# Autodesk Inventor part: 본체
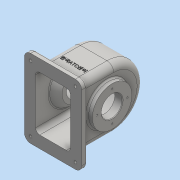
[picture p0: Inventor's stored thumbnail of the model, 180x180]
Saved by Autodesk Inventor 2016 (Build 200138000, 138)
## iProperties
Created: 2018-11
Part Number: 본체
Material: 일반
Document SubType Name: Modeling
Designer: user
Density: 1 g/cm^3
Appearance: 기본값
Mass: 404.475 g
Surface Area: 1182.21 cm^2
Volume: 404.475 cm^3
Author: user
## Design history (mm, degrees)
sketch "스케치1"
  geometry: L1 (-55, -75)-(55, -75); L2 (55, -75)-(55, 75); L3 (55, 75)-(-55, 75); L4 (-55, 75)-(-55, -75); L5 (-55, -75)-(55, 75); L6 (55, -75)-(-55, 75); 1 further point
  constraints: 12 end point, 2 midpoint, 2 parallel, 1 horizontal, 1 perpendicular
  dimensions: "d0" = 110 distance of L3.end L2.end; "d1" = 150 distance of L1.end L2.end
extrude "돌출1" new body sketch "스케치1" distance "d2" = 10; taper "d3" = 0 deg
sketch "스케치2"
  geometry: L1 (-38.5, 58)-(38.5, 58); L2 (38.5, 58)-(38.5, -58); L3 (38.5, -58)-(-38.5, -58); L4 (-38.5, -58)-(-38.5, 58); L5 (-38.5, 58)-(38.5, -58); L6 (38.5, 58)-(-38.5, -58); 1 further point
  constraints: 12 end point, 2 midpoint, 2 parallel, 1 horizontal, 1 perpendicular
  dimensions: "d4" = 77 distance of L2.end L3.end; "d5" = 116 distance of L1.end L2.end
extrude "돌출2" join sketch "스케치2" distance "d6" = 126; taper "d7" = 0 deg
fillet "모깎기1" dims "d8" = 58
feature "쉘1" dims "d13" = 6, "d14" = 5, "d15" = 10
sketch "스케치5"
  geometry: L1 (-17, -10)-(133, -10) reference; C1 r 38 at (58, 55); 2 further points
  constraints: 1 centre point, 1 midpoint, 1 vertical alignment
  dimensions: "d16" = 76 diameter of C1; "d17" = 65 distance from line of C1.centre L1
extrude "돌출4" join sketch "스케치5" distance "d18" = 10; taper "d19" = 0 deg
sketch "스케치6"
  geometry: L1 (-17, -10)-(133, -10) reference; C1 r 38 at (58, 55); 2 further points
  constraints: 1 centre point, 1 midpoint, 1 vertical alignment
  dimensions: "d20" = 76 diameter of C1; "d21" = 65 distance from line of L1 C1.centre
extrude "돌출5" join sketch "스케치6" distance "d22" = 5; taper "d23" = 0 deg
node "작업 평면1"
sketch "스케치7"
  geometry: C1 r 6 at (0, 0); 1 further point
  constraints: 1 centre point, 1 coincident
  dimensions: "d25" = 12 diameter of C1
extrude "돌출6" join sketch "스케치7" stored distance "d26" = 5; taper "d27" = 5 deg
sketch "스케치8"
  geometry: 2 further points
  constraints: 1 coincident
hole "구멍1" sketch "스케치8" at (0, 0) diameter "d28" = 4.459; stored, may be unused: countersink angle "d32" = 90 deg, drill point angle "d34" = 118 deg; dims "d29" = 20, "d30" = 4, "d31" = 2, "d33" = 12.8
node "작업 평면2"
sketch "스케치10"
  geometry: C1 r 28 at (0, 0); 1 further point
  constraints: 1 centre point, 1 vertical alignment
  dimensions: "d36" = 56 diameter of C1; "d37" = 65 distance of C1.centre point (0, -65)
extrude "돌출7" join sketch "스케치10" stored distance "d38" = 5; taper "d39" = 40 deg
sketch "스케치11"
  geometry: L1 (-75, -65)-(75, -65) reference; C1 r 20 at (0, 0); 2 further points
  constraints: 1 centre point, 1 midpoint, 1 vertical alignment
  dimensions: "d40" = 40 diameter of C1; "d41" = 65 distance from line of C1.centre L1
extrude "돌출8" cut sketch "스케치11" stored distance "d42" = 5; taper "d43" = 0 deg
sketch "스케치12"
  geometry: L1 (-75, -65)-(75, -65) reference; C1 r 20 at (0, 0) reference; 3 further points
  constraints: 1 midpoint, 1 vertical alignment
  dimensions: "d44" = 29 distance of point (0, 29) C1.centre
hole "구멍2" sketch "스케치12" at (0, 29) diameter "d45" = 3.242; stored, may be unused: countersink angle "d49" = 90 deg, drill point angle "d51" = 118 deg; dims "d46" = 8, "d47" = 4, "d48" = 2, "d50" = 10
sketch "스케치13"
  geometry: C1 r 20 at (0, 0) reference; 2 further points
  constraints: 1 vertical alignment
  dimensions: "d55" = 29 distance of C1.centre point (0, 29)
hole "구멍3" sketch "스케치13" at (0, 29) diameter "d56" = 3.242; stored, may be unused: countersink angle "d60" = 90 deg, drill point angle "d62" = 118 deg; dims "d57" = 8, "d58" = 4, "d59" = 2, "d61" = 10
fillet "모깎기2" dims "d66" = 12
sketch "스케치14"
  geometry: A1 r 12 centre (43, -63) between (43, -75) and (55, -63) reference; A2 r 12 centre (-43, -63) between (-55, -63) and (-43, -75) reference; A3 r 12 centre (43, 63) between (55, 63) and (43, 75) reference; A4 r 12 centre (-43, 63) between (-43, 75) and (-55, 63) reference; 1 further point
hole "구멍4" sketch "스케치14" at (43, -63), (-43, -63), (43, 63), (-43, 63) diameter "d67" = 5; stored, may be unused: countersink angle "d71" = 90 deg, drill point angle "d73" = 0 deg; dims "d68" = 8, "d69" = 12, "d70" = 4, "d72" = 10
fillet "모깎기3" dims "d74" = 13
fillet "모깎기4" dims "d75" = 3
fillet "모깎기5" dims "d76" = 8
fillet "모깎기6" dims "d77" = 3
sketch "스케치15"
  geometry: L1 (-17.5, -78)-(-29.5, -78) reference; L2 (-13, 0)-(-13, -65) reference; 2 further points
  constraints: 1 other
  dimensions: "d78" = 40 distance from line of point (25.5, -38) L1; "d79" = 38.5 distance from line of point (25.5, -38) L2
feature "엠보싱1" sketch "스케치15" dims "d0" = 110, "d1" = 150, "d80" = 0.5, "d81" = 0
chamfer "모따기1" distance "d82" = 1; stored, may be unused: second distance "d83" = 2, angle "d84" = 45 deg
fillet "모깎기7" dims "d85" = 3
sketch "스케치3"
  geometry: L1 (-17, -10)-(133, -10) reference; C1 r 38 at (58, 55); 2 further points
  constraints: 1 centre point, 1 midpoint, 1 vertical alignment
  dimensions: "d9" = 76 diameter of C1; "d10" = 65 distance from line of C1.centre L1
extrude "돌출3" join sketch "스케치3" distance "d11" = 10; taper "d12" = 0 deg
node "솔리드1"
pattern_circular "원형 패턴1" dims angle "d53" = 360 deg
pattern_circular "원형 패턴2" dims angle "d64" = 360 deg
other parameters: "d24" = 142, "d35" = -24
